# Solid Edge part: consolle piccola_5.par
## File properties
Last saved by: i.fialdini
Revision: 62
Tipo di contenuto documento: 0
Accuracy: 0.990
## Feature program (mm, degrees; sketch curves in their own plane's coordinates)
body "unnamed Body 1"
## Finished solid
Body 1: solid body, 12 faces, 30 edges, 20 vertices.
  Faces by surface: plane 8, cylinder 4
  Edges by curve: line 22, circle 8
Bounding box of the edges (mm): 70.000 x 416.000 x 2.000, from (-249.5, -924.1568, 700.9818) to (-179.5, -508.1568, 702.9818).
Cylindrical faces by radius (mm): R5 x2, R40 x2
Planar faces by outward normal: +x 2, +y 1, +z 1, -x 2, -y 1, -z 1
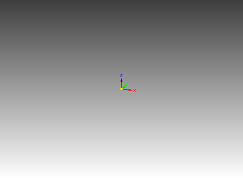
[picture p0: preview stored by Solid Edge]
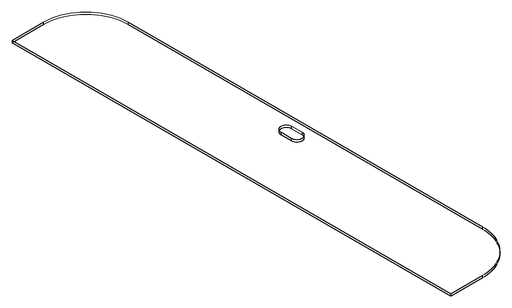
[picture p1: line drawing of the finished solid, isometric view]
